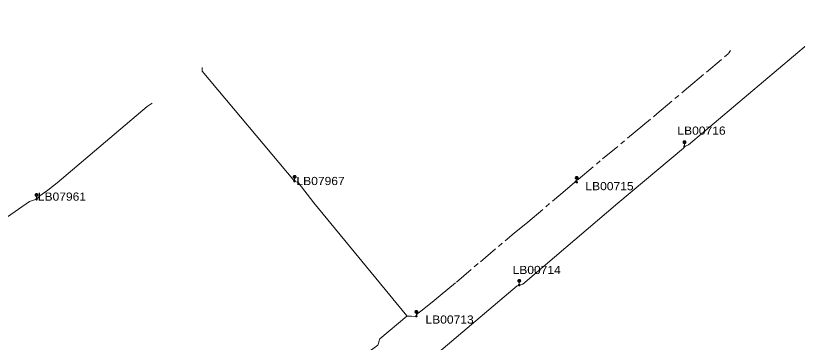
# Model space of a CAD drawing. Extents: x -688049 to -687261, y -973611 to -973038.
# Drawn here: x -687889.6 to -687682.8, y -973124.8 to -973038.3 of the extents above; entities that cross this region are included whole.
import ezdxf

# ---------------------------------------------------------------- set-up
doc = ezdxf.new("R2010")
doc.units = 0
doc.header["$LTSCALE"] = 0.87
doc.linetypes.add('LONG_DASH_SHORT_DASH', pattern=[9.9, 6, -1.2, 1.5, -1.2])
doc.layers.add('1', color=7, linetype='Continuous', lineweight=13)

msp = doc.modelspace()

# ---------------------------------------------------------------- linework, layer by layer
at = {"layer": '1'}
for p, q in [((-687712.915, -973071.535), (-687712.385, -973072.065)), ((-687712.915, -973072.065), (-687712.385, -973071.535)), ((-687712.65, -973072.95), (-687712.65, -973072.175)), ((-687816.075, -973080.735), (-687815.545, -973081.265)), ((-687816.075, -973081.265), (-687815.545, -973080.735)), ((-687815.81, -973082.15), (-687815.81, -973081.375)), ((-687741.423, -973081.005), (-687740.893, -973081.535)), ((-687741.423, -973081.535), (-687740.893, -973081.005)), ((-687741.43, -973082.01), (-687741.16, -973082.42)), ((-687741.158, -973082.42), (-687741.158, -973081.645)), ((-687884.385, -973085.525), (-687883.855, -973086.055)), ((-687884.385, -973086.055), (-687883.855, -973085.525)), ((-687884.12, -973086.94), (-687884.12, -973086.165)), ((-687756.625, -973108.245), (-687756.095, -973108.775)), ((-687756.625, -973108.775), (-687756.095, -973108.245)), ((-687756.36, -973109.66), (-687756.36, -973108.885)), ((-687783.845, -973116.475), (-687783.315, -973117.005)), ((-687783.845, -973117.005), (-687783.315, -973116.475)), ((-687783.58, -973117.89), (-687783.58, -973117.115))]:
    msp.add_line(p, q, dxfattribs=at)
at = {"layer": '1', "linetype": 'LONG_DASH_SHORT_DASH'}
msp.add_line((-687741.43, -973082.01), (-687741.16, -973082.42), dxfattribs=at)
at = {"layer": '1'}
for points in [[(-687712.65, -973072.95), (-687711.559, -973072.486), (-687671.844, -973038.989), (-687671.482, -973038.307)], [(-687815.81, -973082.15), (-687840.27, -973053.047), (-687840.269, -973052.066)], [(-687853.54, -973061.52), (-687854.799, -973062.35), (-687878.624, -973082.554), (-687881.098, -973084.555), (-687883.189, -973085.993), (-687884.12, -973086.94)], [(-687756.36, -973109.66), (-687755.413, -973109.375), (-687730.31, -973087.957), (-687712.919, -973073.436), (-687712.65, -973072.95)], [(-687783.63, -973117.93), (-687786.092, -973117.805), (-687810.703, -973087.832), (-687814.851, -973082.485), (-687815.81, -973082.15)], [(-687884.12, -973086.94), (-687885.926, -973087.5), (-687891.829, -973091.595), (-687911.101, -973101.785), (-687912.338, -973102.386), (-687913.07, -973103.17)], [(-687756.36, -973109.66), (-687756.954, -973109.852), (-687798.405, -973144.971), (-687798.86, -973145.34)], [(-687797.06, -973127.92), (-687797.06, -973127.92), (-687793.746, -973125.582), (-687793.273, -973123.922), (-687786.073, -973117.922), (-687783.63, -973117.93)]]:
    msp.add_lwpolyline(points, dxfattribs=at)
at = {"layer": '1', "linetype": 'LONG_DASH_SHORT_DASH'}
for points in [[(-687741.43, -973082.01), (-687740.76, -973081.66), (-687734.31, -973076.25), (-687725.68, -973069.1), (-687719.95, -973064.32), (-687711.57, -973057.28), (-687706.82, -973053.3), (-687701.01, -973048.33), (-687700.5, -973047.55)], [(-687783.58, -973117.89), (-687783.59, -973117.41), (-687782.38, -973116.54), (-687779.38, -973114.18), (-687777.29, -973112.4), (-687773.01, -973108.9), (-687766.66, -973103.46), (-687757.73, -973095.91), (-687754.09, -973092.99), (-687745.35, -973085.54), (-687741.74, -973082.46), (-687741.43, -973082.01)]]:
    msp.add_lwpolyline(points, dxfattribs=at)
at = {"layer": '1'}
for points in [[(-687712.275, -973071.8), (-687712.281, -973071.735), (-687712.298, -973071.672), (-687712.325, -973071.612), (-687712.363, -973071.559), (-687712.409, -973071.513), (-687712.462, -973071.475), (-687712.522, -973071.448), (-687712.585, -973071.431), (-687712.65, -973071.425), (-687712.715, -973071.431), (-687712.778, -973071.448), (-687712.838, -973071.475), (-687712.891, -973071.513), (-687712.937, -973071.559), (-687712.975, -973071.612), (-687713.002, -973071.672), (-687713.019, -973071.735), (-687713.025, -973071.8), (-687713.019, -973071.865), (-687713.002, -973071.928), (-687712.975, -973071.987), (-687712.937, -973072.041), (-687712.891, -973072.087), (-687712.838, -973072.125), (-687712.778, -973072.152), (-687712.715, -973072.169), (-687712.65, -973072.175), (-687712.585, -973072.169), (-687712.522, -973072.152), (-687712.462, -973072.125), (-687712.409, -973072.087), (-687712.363, -973072.041), (-687712.325, -973071.987), (-687712.298, -973071.928), (-687712.281, -973071.865)], [(-687712.46, -973072.95), (-687712.463, -973072.917), (-687712.471, -973072.885), (-687712.485, -973072.855), (-687712.504, -973072.828), (-687712.528, -973072.804), (-687712.555, -973072.785), (-687712.585, -973072.771), (-687712.617, -973072.763), (-687712.65, -973072.76), (-687712.683, -973072.763), (-687712.715, -973072.771), (-687712.745, -973072.785), (-687712.772, -973072.804), (-687712.796, -973072.828), (-687712.815, -973072.855), (-687712.829, -973072.885), (-687712.837, -973072.917), (-687712.84, -973072.95), (-687712.837, -973072.983), (-687712.829, -973073.015), (-687712.815, -973073.045), (-687712.796, -973073.072), (-687712.772, -973073.096), (-687712.745, -973073.115), (-687712.715, -973073.129), (-687712.683, -973073.137), (-687712.65, -973073.14), (-687712.617, -973073.137), (-687712.585, -973073.129), (-687712.555, -973073.115), (-687712.528, -973073.096), (-687712.504, -973073.072), (-687712.485, -973073.045), (-687712.471, -973073.015), (-687712.463, -973072.983)], [(-687712.6, -973072.95), (-687712.601, -973072.941), (-687712.603, -973072.933), (-687712.607, -973072.925), (-687712.612, -973072.918), (-687712.618, -973072.912), (-687712.625, -973072.907), (-687712.633, -973072.903), (-687712.641, -973072.901), (-687712.65, -973072.9), (-687712.659, -973072.901), (-687712.667, -973072.903), (-687712.675, -973072.907), (-687712.682, -973072.912), (-687712.688, -973072.918), (-687712.693, -973072.925), (-687712.697, -973072.933), (-687712.699, -973072.941), (-687712.7, -973072.95), (-687712.699, -973072.959), (-687712.697, -973072.967), (-687712.693, -973072.975), (-687712.688, -973072.982), (-687712.682, -973072.988), (-687712.675, -973072.993), (-687712.667, -973072.997), (-687712.659, -973072.999), (-687712.65, -973073), (-687712.641, -973072.999), (-687712.633, -973072.997), (-687712.625, -973072.993), (-687712.618, -973072.988), (-687712.612, -973072.982), (-687712.607, -973072.975), (-687712.603, -973072.967), (-687712.601, -973072.959)], [(-687815.435, -973081), (-687815.441, -973080.935), (-687815.458, -973080.872), (-687815.485, -973080.812), (-687815.523, -973080.759), (-687815.569, -973080.713), (-687815.622, -973080.675), (-687815.682, -973080.648), (-687815.745, -973080.631), (-687815.81, -973080.625), (-687815.875, -973080.631), (-687815.938, -973080.648), (-687815.998, -973080.675), (-687816.051, -973080.713), (-687816.097, -973080.759), (-687816.135, -973080.812), (-687816.162, -973080.872), (-687816.179, -973080.935), (-687816.185, -973081), (-687816.179, -973081.065), (-687816.162, -973081.128), (-687816.135, -973081.188), (-687816.097, -973081.241), (-687816.051, -973081.287), (-687815.998, -973081.325), (-687815.938, -973081.352), (-687815.875, -973081.369), (-687815.81, -973081.375), (-687815.745, -973081.369), (-687815.682, -973081.352), (-687815.622, -973081.325), (-687815.569, -973081.287), (-687815.523, -973081.241), (-687815.485, -973081.188), (-687815.458, -973081.128), (-687815.441, -973081.065)], [(-687740.783, -973081.27), (-687740.789, -973081.205), (-687740.806, -973081.142), (-687740.833, -973081.082), (-687740.871, -973081.029), (-687740.917, -973080.983), (-687740.97, -973080.945), (-687741.03, -973080.918), (-687741.093, -973080.901), (-687741.158, -973080.895), (-687741.223, -973080.901), (-687741.286, -973080.918), (-687741.346, -973080.945), (-687741.399, -973080.983), (-687741.445, -973081.029), (-687741.483, -973081.082), (-687741.51, -973081.142), (-687741.527, -973081.205), (-687741.533, -973081.27), (-687741.527, -973081.335), (-687741.51, -973081.398), (-687741.483, -973081.458), (-687741.445, -973081.511), (-687741.399, -973081.557), (-687741.346, -973081.595), (-687741.286, -973081.622), (-687741.223, -973081.639), (-687741.158, -973081.645), (-687741.093, -973081.639), (-687741.03, -973081.622), (-687740.97, -973081.595), (-687740.917, -973081.557), (-687740.871, -973081.511), (-687740.833, -973081.458), (-687740.806, -973081.398), (-687740.789, -973081.335)], [(-687815.62, -973082.15), (-687815.623, -973082.117), (-687815.631, -973082.085), (-687815.645, -973082.055), (-687815.664, -973082.028), (-687815.688, -973082.004), (-687815.715, -973081.985), (-687815.745, -973081.971), (-687815.777, -973081.963), (-687815.81, -973081.96), (-687815.843, -973081.963), (-687815.875, -973081.971), (-687815.905, -973081.985), (-687815.932, -973082.004), (-687815.956, -973082.028), (-687815.975, -973082.055), (-687815.989, -973082.085), (-687815.997, -973082.117), (-687816, -973082.15), (-687815.997, -973082.183), (-687815.989, -973082.215), (-687815.975, -973082.245), (-687815.956, -973082.272), (-687815.932, -973082.296), (-687815.905, -973082.315), (-687815.875, -973082.329), (-687815.843, -973082.337), (-687815.81, -973082.34), (-687815.777, -973082.337), (-687815.745, -973082.329), (-687815.715, -973082.315), (-687815.688, -973082.296), (-687815.664, -973082.272), (-687815.645, -973082.245), (-687815.631, -973082.215), (-687815.623, -973082.183)], [(-687815.76, -973082.15), (-687815.761, -973082.141), (-687815.763, -973082.133), (-687815.767, -973082.125), (-687815.772, -973082.118), (-687815.778, -973082.112), (-687815.785, -973082.107), (-687815.793, -973082.103), (-687815.801, -973082.101), (-687815.81, -973082.1), (-687815.819, -973082.101), (-687815.827, -973082.103), (-687815.835, -973082.107), (-687815.842, -973082.112), (-687815.848, -973082.118), (-687815.853, -973082.125), (-687815.857, -973082.133), (-687815.859, -973082.141), (-687815.86, -973082.15), (-687815.859, -973082.159), (-687815.857, -973082.167), (-687815.853, -973082.175), (-687815.848, -973082.182), (-687815.842, -973082.188), (-687815.835, -973082.193), (-687815.827, -973082.197), (-687815.819, -973082.199), (-687815.81, -973082.2), (-687815.801, -973082.199), (-687815.793, -973082.197), (-687815.785, -973082.193), (-687815.778, -973082.188), (-687815.772, -973082.182), (-687815.767, -973082.175), (-687815.763, -973082.167), (-687815.761, -973082.159)], [(-687740.968, -973082.42), (-687740.971, -973082.387), (-687740.979, -973082.355), (-687740.993, -973082.325), (-687741.012, -973082.298), (-687741.036, -973082.274), (-687741.063, -973082.255), (-687741.093, -973082.241), (-687741.125, -973082.233), (-687741.158, -973082.23), (-687741.191, -973082.233), (-687741.223, -973082.241), (-687741.253, -973082.255), (-687741.28, -973082.274), (-687741.304, -973082.298), (-687741.323, -973082.325), (-687741.337, -973082.355), (-687741.345, -973082.387), (-687741.348, -973082.42), (-687741.345, -973082.453), (-687741.337, -973082.485), (-687741.323, -973082.515), (-687741.304, -973082.542), (-687741.28, -973082.566), (-687741.253, -973082.585), (-687741.223, -973082.599), (-687741.191, -973082.607), (-687741.158, -973082.61), (-687741.125, -973082.607), (-687741.093, -973082.599), (-687741.063, -973082.585), (-687741.036, -973082.566), (-687741.012, -973082.542), (-687740.993, -973082.515), (-687740.979, -973082.485), (-687740.971, -973082.453)], [(-687741.108, -973082.42), (-687741.109, -973082.411), (-687741.111, -973082.403), (-687741.115, -973082.395), (-687741.12, -973082.388), (-687741.126, -973082.382), (-687741.133, -973082.377), (-687741.141, -973082.373), (-687741.149, -973082.371), (-687741.158, -973082.37), (-687741.167, -973082.371), (-687741.175, -973082.373), (-687741.183, -973082.377), (-687741.19, -973082.382), (-687741.196, -973082.388), (-687741.201, -973082.395), (-687741.205, -973082.403), (-687741.207, -973082.411), (-687741.208, -973082.42), (-687741.207, -973082.429), (-687741.205, -973082.437), (-687741.201, -973082.445), (-687741.196, -973082.452), (-687741.19, -973082.458), (-687741.183, -973082.463), (-687741.175, -973082.467), (-687741.167, -973082.469), (-687741.158, -973082.47), (-687741.149, -973082.469), (-687741.141, -973082.467), (-687741.133, -973082.463), (-687741.126, -973082.458), (-687741.12, -973082.452), (-687741.115, -973082.445), (-687741.111, -973082.437), (-687741.109, -973082.429)], [(-687883.745, -973085.79), (-687883.751, -973085.725), (-687883.768, -973085.662), (-687883.795, -973085.602), (-687883.833, -973085.549), (-687883.879, -973085.503), (-687883.932, -973085.465), (-687883.992, -973085.438), (-687884.055, -973085.421), (-687884.12, -973085.415), (-687884.185, -973085.421), (-687884.248, -973085.438), (-687884.308, -973085.465), (-687884.361, -973085.503), (-687884.407, -973085.549), (-687884.445, -973085.602), (-687884.472, -973085.662), (-687884.489, -973085.725), (-687884.495, -973085.79), (-687884.489, -973085.855), (-687884.472, -973085.918), (-687884.445, -973085.977), (-687884.407, -973086.031), (-687884.361, -973086.077), (-687884.308, -973086.115), (-687884.248, -973086.142), (-687884.185, -973086.159), (-687884.12, -973086.165), (-687884.055, -973086.159), (-687883.992, -973086.142), (-687883.932, -973086.115), (-687883.879, -973086.077), (-687883.833, -973086.031), (-687883.795, -973085.977), (-687883.768, -973085.918), (-687883.751, -973085.855)], [(-687883.93, -973086.94), (-687883.933, -973086.907), (-687883.941, -973086.875), (-687883.955, -973086.845), (-687883.974, -973086.818), (-687883.998, -973086.794), (-687884.025, -973086.775), (-687884.055, -973086.761), (-687884.087, -973086.753), (-687884.12, -973086.75), (-687884.153, -973086.753), (-687884.185, -973086.761), (-687884.215, -973086.775), (-687884.242, -973086.794), (-687884.266, -973086.818), (-687884.285, -973086.845), (-687884.299, -973086.875), (-687884.307, -973086.907), (-687884.31, -973086.94), (-687884.307, -973086.973), (-687884.299, -973087.005), (-687884.285, -973087.035), (-687884.266, -973087.062), (-687884.242, -973087.086), (-687884.215, -973087.105), (-687884.185, -973087.119), (-687884.153, -973087.127), (-687884.12, -973087.13), (-687884.087, -973087.127), (-687884.055, -973087.119), (-687884.025, -973087.105), (-687883.998, -973087.086), (-687883.974, -973087.062), (-687883.955, -973087.035), (-687883.941, -973087.005), (-687883.933, -973086.973)], [(-687884.07, -973086.94), (-687884.071, -973086.931), (-687884.073, -973086.923), (-687884.077, -973086.915), (-687884.082, -973086.908), (-687884.088, -973086.902), (-687884.095, -973086.897), (-687884.103, -973086.893), (-687884.111, -973086.891), (-687884.12, -973086.89), (-687884.129, -973086.891), (-687884.137, -973086.893), (-687884.145, -973086.897), (-687884.152, -973086.902), (-687884.158, -973086.908), (-687884.163, -973086.915), (-687884.167, -973086.923), (-687884.169, -973086.931), (-687884.17, -973086.94), (-687884.169, -973086.949), (-687884.167, -973086.957), (-687884.163, -973086.965), (-687884.158, -973086.972), (-687884.152, -973086.978), (-687884.145, -973086.983), (-687884.137, -973086.987), (-687884.129, -973086.989), (-687884.12, -973086.99), (-687884.111, -973086.989), (-687884.103, -973086.987), (-687884.095, -973086.983), (-687884.088, -973086.978), (-687884.082, -973086.972), (-687884.077, -973086.965), (-687884.073, -973086.957), (-687884.071, -973086.949)], [(-687755.985, -973108.51), (-687755.991, -973108.445), (-687756.008, -973108.382), (-687756.035, -973108.322), (-687756.073, -973108.269), (-687756.119, -973108.223), (-687756.172, -973108.185), (-687756.232, -973108.158), (-687756.295, -973108.141), (-687756.36, -973108.135), (-687756.425, -973108.141), (-687756.488, -973108.158), (-687756.548, -973108.185), (-687756.601, -973108.223), (-687756.647, -973108.269), (-687756.685, -973108.322), (-687756.712, -973108.382), (-687756.729, -973108.445), (-687756.735, -973108.51), (-687756.729, -973108.575), (-687756.712, -973108.638), (-687756.685, -973108.698), (-687756.647, -973108.751), (-687756.601, -973108.797), (-687756.548, -973108.835), (-687756.488, -973108.862), (-687756.425, -973108.879), (-687756.36, -973108.885), (-687756.295, -973108.879), (-687756.232, -973108.862), (-687756.172, -973108.835), (-687756.119, -973108.797), (-687756.073, -973108.751), (-687756.035, -973108.698), (-687756.008, -973108.638), (-687755.991, -973108.575)], [(-687756.17, -973109.66), (-687756.173, -973109.627), (-687756.181, -973109.595), (-687756.195, -973109.565), (-687756.214, -973109.538), (-687756.238, -973109.514), (-687756.265, -973109.495), (-687756.295, -973109.481), (-687756.327, -973109.473), (-687756.36, -973109.47), (-687756.393, -973109.473), (-687756.425, -973109.481), (-687756.455, -973109.495), (-687756.482, -973109.514), (-687756.506, -973109.538), (-687756.525, -973109.565), (-687756.539, -973109.595), (-687756.547, -973109.627), (-687756.55, -973109.66), (-687756.547, -973109.693), (-687756.539, -973109.725), (-687756.525, -973109.755), (-687756.506, -973109.782), (-687756.482, -973109.806), (-687756.455, -973109.825), (-687756.425, -973109.839), (-687756.393, -973109.847), (-687756.36, -973109.85), (-687756.327, -973109.847), (-687756.295, -973109.839), (-687756.265, -973109.825), (-687756.238, -973109.806), (-687756.214, -973109.782), (-687756.195, -973109.755), (-687756.181, -973109.725), (-687756.173, -973109.693)], [(-687756.31, -973109.66), (-687756.311, -973109.651), (-687756.313, -973109.643), (-687756.317, -973109.635), (-687756.322, -973109.628), (-687756.328, -973109.622), (-687756.335, -973109.617), (-687756.343, -973109.613), (-687756.351, -973109.611), (-687756.36, -973109.61), (-687756.369, -973109.611), (-687756.377, -973109.613), (-687756.385, -973109.617), (-687756.392, -973109.622), (-687756.398, -973109.628), (-687756.403, -973109.635), (-687756.407, -973109.643), (-687756.409, -973109.651), (-687756.41, -973109.66), (-687756.409, -973109.669), (-687756.407, -973109.677), (-687756.403, -973109.685), (-687756.398, -973109.692), (-687756.392, -973109.698), (-687756.385, -973109.703), (-687756.377, -973109.707), (-687756.369, -973109.709), (-687756.36, -973109.71), (-687756.351, -973109.709), (-687756.343, -973109.707), (-687756.335, -973109.703), (-687756.328, -973109.698), (-687756.322, -973109.692), (-687756.317, -973109.685), (-687756.313, -973109.677), (-687756.311, -973109.669)], [(-687783.205, -973116.74), (-687783.211, -973116.675), (-687783.228, -973116.612), (-687783.255, -973116.552), (-687783.293, -973116.499), (-687783.339, -973116.453), (-687783.392, -973116.415), (-687783.452, -973116.388), (-687783.515, -973116.371), (-687783.58, -973116.365), (-687783.645, -973116.371), (-687783.708, -973116.388), (-687783.768, -973116.415), (-687783.821, -973116.453), (-687783.867, -973116.499), (-687783.905, -973116.552), (-687783.932, -973116.612), (-687783.949, -973116.675), (-687783.955, -973116.74), (-687783.949, -973116.805), (-687783.932, -973116.868), (-687783.905, -973116.928), (-687783.867, -973116.981), (-687783.821, -973117.027), (-687783.768, -973117.065), (-687783.708, -973117.092), (-687783.645, -973117.109), (-687783.58, -973117.115), (-687783.515, -973117.109), (-687783.452, -973117.092), (-687783.392, -973117.065), (-687783.339, -973117.027), (-687783.293, -973116.981), (-687783.255, -973116.928), (-687783.228, -973116.868), (-687783.211, -973116.805)], [(-687783.39, -973117.89), (-687783.393, -973117.857), (-687783.401, -973117.825), (-687783.415, -973117.795), (-687783.434, -973117.768), (-687783.458, -973117.744), (-687783.485, -973117.725), (-687783.515, -973117.711), (-687783.547, -973117.703), (-687783.58, -973117.7), (-687783.613, -973117.703), (-687783.645, -973117.711), (-687783.675, -973117.725), (-687783.702, -973117.744), (-687783.726, -973117.768), (-687783.745, -973117.795), (-687783.759, -973117.825), (-687783.767, -973117.857), (-687783.77, -973117.89), (-687783.767, -973117.923), (-687783.759, -973117.955), (-687783.745, -973117.985), (-687783.726, -973118.012), (-687783.702, -973118.036), (-687783.675, -973118.055), (-687783.645, -973118.069), (-687783.613, -973118.077), (-687783.58, -973118.08), (-687783.547, -973118.077), (-687783.515, -973118.069), (-687783.485, -973118.055), (-687783.458, -973118.036), (-687783.434, -973118.012), (-687783.415, -973117.985), (-687783.401, -973117.955), (-687783.393, -973117.923)], [(-687783.53, -973117.89), (-687783.531, -973117.881), (-687783.533, -973117.873), (-687783.537, -973117.865), (-687783.542, -973117.858), (-687783.548, -973117.852), (-687783.555, -973117.847), (-687783.563, -973117.843), (-687783.571, -973117.841), (-687783.58, -973117.84), (-687783.589, -973117.841), (-687783.597, -973117.843), (-687783.605, -973117.847), (-687783.612, -973117.852), (-687783.618, -973117.858), (-687783.623, -973117.865), (-687783.627, -973117.873), (-687783.629, -973117.881), (-687783.63, -973117.89), (-687783.629, -973117.899), (-687783.627, -973117.907), (-687783.623, -973117.915), (-687783.618, -973117.922), (-687783.612, -973117.928), (-687783.605, -973117.933), (-687783.597, -973117.937), (-687783.589, -973117.939), (-687783.58, -973117.94), (-687783.571, -973117.939), (-687783.563, -973117.937), (-687783.555, -973117.933), (-687783.548, -973117.928), (-687783.542, -973117.922), (-687783.537, -973117.915), (-687783.533, -973117.907), (-687783.531, -973117.899)]]:
    msp.add_lwpolyline(points, close=True, dxfattribs=at)

# ---------------------------------------------------------------- texts
at = {"layer": '1', "width": 1.1}
for s, p in [('LB00716', (-687714.518, -973069.835)), ('LB07967', (-687815.317, -973083.174)), ('LB00715', (-687738.865, -973084.542)), ('LB07961', (-687883.76, -973087.312)), ('LB00714', (-687758.131, -973106.729)), ('LB00713', (-687781.177, -973119.858))]:
    msp.add_text(s, height=2.167, dxfattribs=at).set_placement(p)

doc.saveas('drawing.dxf')
